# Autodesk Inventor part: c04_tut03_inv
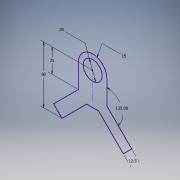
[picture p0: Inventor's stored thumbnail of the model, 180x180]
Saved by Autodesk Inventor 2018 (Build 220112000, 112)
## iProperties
Created: 2017-04
Part Number: c04_tut03_inv
Material: Generic
Document SubType Name: Modeling
Designer: CADCIM 00
Density: 1 g/cm^3
Appearance: Default
Author: CADCIM 00
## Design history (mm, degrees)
sketch "Sketch1"
  geometry: L1 (-6.25, -33.928)-(6.25, -33.928); L2 (6.25, -33.928)-(32.322, -60); L3 (32.322, -60)-(41.161, -51.161); L4 (41.161, -51.161)-(15, -25); L5 (15, -25)-(15, 0); L6 (-15, 0)-(-15, -25); L7 (-15, -25)-(-41.161, -51.161); L8 (-41.161, -51.161)-(-32.322, -60); L9 (-32.322, -60)-(-6.25, -33.928); L10 (0, 0)-(0, -28.219); C1 r 10 at (0, 0); A1 r 15 centre (0, 0) between (15, 0) and (-15, 0); 1 further point
  constraints: 20 end point, 5 perpendicular, 2 centre point, 2 coincident, 2 point on circle, 2 symmetric about line, 2 tangent, 1 concentric, 1 equal length, 1 horizontal, 1 parallel, 1 point on line, 1 vertical, 2 other
  dimensions: "d0" = 15 radius of A1; "d1" = 135 deg angle of L7 L6; "d2" = 12.5 distance of L7.end L8.end; "d3" = 60 vertical distance of L2.end L10.start; "d4" = 25 vertical distance of L10.start L4.end; "d5" = 20 diameter of C1
